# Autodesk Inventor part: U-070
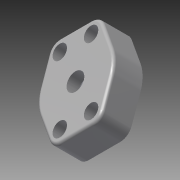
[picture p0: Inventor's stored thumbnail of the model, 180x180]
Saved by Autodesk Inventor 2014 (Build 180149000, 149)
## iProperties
Created: 2011-01
Part Number: U-070
Material: Steel
Document SubType Name: Modeling
Designer: deckm
Density: 7.85 g/cm^3
Description: FLARED FLANGE SAE WITH CLEARANCE HOLES
Mass: 259.498 g
Surface Area: 100.719 cm^2
Volume: 33.0571 cm^3
Appearance: Steel
Author: deckm
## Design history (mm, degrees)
derived "union_cap.ipt"
body "Solid1"
feature "Solid1::union_cap.ipt"
tag "TaggingFeature1"
other parameters: "d1" = 65.024, "d3" = 19.10263, "d25" = 22.352, "FilletTop" = 2, "d27" = 9.525, "d28" = 37 deg, "d29" = 20.828, "d30" = 6.35, "FilletCorners" = 8.636, "FilletEnds" = 26.162, "d8" = 20.828, "d9" = 0, "d12" = 10.31875, "d21" = 22.352, "d24" = 47.752
